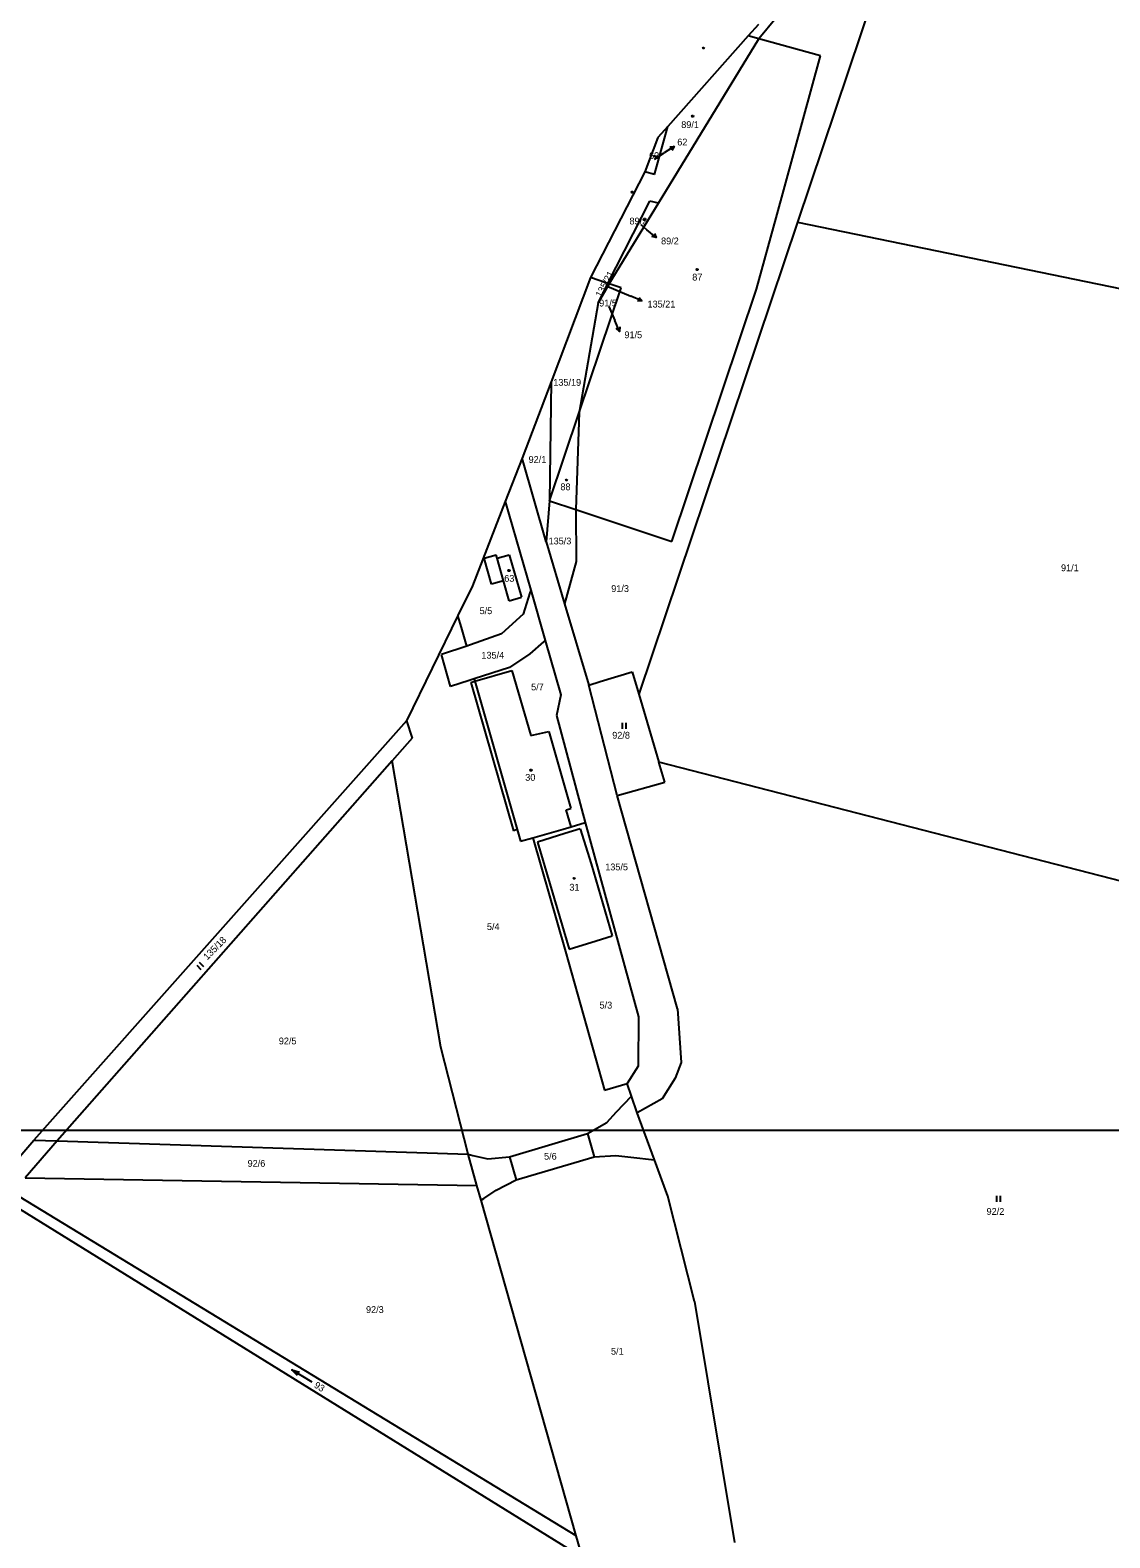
# Model space of a CAD drawing. Extents: x -752500 to -750336, y -1035826 to -1033500.
# Drawn here: x -751866.1 to -751596.3, y -1034101.8 to -1033725.2 of the extents above; entities that cross this region are included whole.
import ezdxf

# ---------------------------------------------------------------- set-up
doc = ezdxf.new("R2010")
doc.units = 0
for name, color, linetype in [('Default', 7, 'Continuous'), ('Hranice kat_území', 7, 'Continuous'), ('Hranice parcel', 7, 'Continuous'), ('ML1000', 7, 'Continuous'), ('Parcelní čísla', 7, 'Continuous'), ('Pop  PČ popisy', 7, 'Continuous'), ('Vnitřní kresba', 7, 'Continuous'), ('Značky budov', 7, 'Continuous'), ('Značky kultur', 7, 'Continuous')]:
    doc.layers.add(name, color=color, linetype=linetype)

# ---------------------------------------------------------------- blocks, each defined once
blk = doc.blocks.new('306')
at = {"layer": 'Default'}
for p, q in [((-0.5, 1.5), (-0.5, 0)), ((0.5, 0), (0.5, 1.5))]:
    blk.add_line(p, q, dxfattribs=at)
blk = doc.blocks.new('802')
at = {"layer": 'Default'}
blk.add_line((-3, 0), (3, 0), dxfattribs=at)
blk.add_lwpolyline([(1, 0.5), (3, 0), (1, -0.5)], dxfattribs=at)
blk = doc.blocks.new('10292')
at = {"layer": 'Default'}
blk.add_line((0, 3), (0, 0), dxfattribs=at)
blk.add_lwpolyline([(-0.5, 2), (0, 3), (0.5, 2)], dxfattribs=at)
blk = doc.blocks.new('402')
at = {"layer": 'Default'}
blk.add_lwpolyline([(0.09, 0.15), (0.18, 0), (0.09, -0.15), (-0.09, -0.15), (-0.18, 0), (-0.09, 0.15), (0.09, 0.15)], dxfattribs=at)

msp = doc.modelspace()

# ---------------------------------------------------------------- linework, layer by layer
at = {"layer": 'Hranice kat_území'}
for p, q in [((-751686.7, -1033726.57), (-751706.79, -1033749.21)), ((-751684.07, -1033723.74), (-751686.7, -1033726.57)), ((-751706.79, -1033749.21), (-751709.24, -1033751.97)), ((-751709.24, -1033751.97), (-751712.49, -1033760.52)), ((-751712.49, -1033760.52), (-751726.1, -1033786.95)), ((-751726.1, -1033786.95), (-751735.93, -1033813.02)), ((-751735.93, -1033813.02), (-751743.12, -1033832.07)), ((-751743.12, -1033832.07), (-751747.38, -1033842.95)), ((-751747.38, -1033842.95), (-751755.6, -1033863.97)), ((-751755.6, -1033863.97), (-751759.23, -1033871.39)), ((-751759.23, -1033871.39), (-751772.1, -1033897.72)), ((-751772.1, -1033897.72), (-751865.22, -1034002.43)), ((-751900.01, -1034043.01), (-751865.22, -1034002.43))]:
    msp.add_line(p, q, dxfattribs=at)
at = {"layer": 'Hranice parcel'}
for p, q in [((-751649.5, -1033699.28), (-751674.33, -1033773.12)), ((-751671.51, -1033712.21), (-751684.01, -1033727.32)), ((-751684.01, -1033727.32), (-751686.7, -1033726.57)), ((-751709.08, -1033768.39), (-751684.01, -1033727.32)), ((-751668.6, -1033731.57), (-751684.01, -1033727.32)), ((-751679.67, -1033772.02), (-751668.6, -1033731.57)), ((-751710.08, -1033761.2), (-751706.79, -1033749.21)), ((-751710.08, -1033761.2), (-751712.49, -1033760.52)), ((-751721.77, -1033788.42), (-751711.24, -1033767.89)), ((-751721.39, -1033788.55), (-751709.08, -1033768.39)), ((-751709.08, -1033768.39), (-751711.24, -1033767.89)), ((-751684.56, -1033789.88), (-751679.67, -1033772.02)), ((-751674.33, -1033773.12), (-751714, -1033891.06)), ((-751674.33, -1033773.12), (-751500.87, -1033808.86)), ((-751721.77, -1033788.42), (-751726.1, -1033786.95)), ((-751728.9, -1033820.71), (-751718.44, -1033789.55)), ((-751724.13, -1033793.3), (-751721.77, -1033788.42)), ((-751721.39, -1033788.55), (-751724.13, -1033793.3)), ((-751721.39, -1033788.55), (-751721.77, -1033788.42)), ((-751718.44, -1033789.55), (-751721.39, -1033788.55)), ((-751705.73, -1033852.93), (-751684.56, -1033789.88)), ((-751724.13, -1033793.3), (-751728.9, -1033820.71)), ((-751735.93, -1033813.02), (-751736.29, -1033842.73)), ((-751736.29, -1033842.73), (-751728.9, -1033820.71)), ((-751728.9, -1033820.71), (-751729.71, -1033844.93)), ((-751737.18, -1033852.97), (-751743.12, -1033832.07)), ((-751747.38, -1033842.95), (-751740.99, -1033865.03)), ((-751736.29, -1033842.73), (-751737.18, -1033852.97)), ((-751736.29, -1033842.73), (-751729.71, -1033844.93)), ((-751729.71, -1033844.93), (-751705.73, -1033852.93)), ((-751729.71, -1033844.93), (-751729.68, -1033857.86)), ((-751737.18, -1033852.97), (-751732.54, -1033868.49)), ((-751752.63, -1033857.07), (-751749.65, -1033856.23)), ((-751750.79, -1033863.54), (-751752.63, -1033857.07)), ((-751749.4, -1033857.1), (-751749.65, -1033856.23)), ((-751749.4, -1033857.1), (-751746.42, -1033856.24)), ((-751746.42, -1033856.24), (-751743.33, -1033866.83)), ((-751729.68, -1033857.86), (-751732.54, -1033868.49)), ((-751747.81, -1033862.69), (-751750.79, -1033863.54)), ((-751746.39, -1033867.7), (-751747.81, -1033862.69)), ((-751741.21, -1033865.7), (-751742.93, -1033871.04)), ((-751740.99, -1033865.03), (-751741.21, -1033865.7)), ((-751740.99, -1033865.03), (-751737.37, -1033877.6)), ((-751746.39, -1033867.7), (-751743.33, -1033866.83)), ((-751732.54, -1033868.49), (-751726.47, -1033888.81)), ((-751742.93, -1033871.04), (-751748.35, -1033875.98)), ((-751748.35, -1033875.98), (-751756.09, -1033878.73)), ((-751737.37, -1033877.6), (-751737.82, -1033877.99)), ((-751737.37, -1033877.6), (-751733.48, -1033891.19)), ((-751756.97, -1033879.02), (-751763.29, -1033881.13)), ((-751761.06, -1033889.12), (-751763.29, -1033881.13)), ((-751756.09, -1033878.73), (-751756.97, -1033879.02)), ((-751741.23, -1033880.94), (-751746.31, -1033884.36)), ((-751737.82, -1033877.99), (-751741.23, -1033880.94)), ((-751746.31, -1033884.36), (-751755.12, -1033887.2)), ((-751754.96, -1033887.81), (-751745.73, -1033885.12)), ((-751745.73, -1033885.12), (-751740.96, -1033901.39)), ((-751756.41, -1033887.62), (-751761.06, -1033889.12)), ((-751755.12, -1033887.2), (-751756.41, -1033887.62)), ((-751755.96, -1033888.09), (-751754.96, -1033887.81)), ((-751755.96, -1033888.09), (-751745.29, -1033925.15)), ((-751755.12, -1033887.2), (-751754.96, -1033887.81)), ((-751726.47, -1033888.81), (-751723.64, -1033887.9)), ((-751719.38, -1033916.32), (-751726.47, -1033888.81)), ((-751723.64, -1033887.9), (-751715.65, -1033885.47)), ((-751715.65, -1033885.47), (-751714, -1033891.06)), ((-751733.48, -1033891.19), (-751734.54, -1033896.35)), ((-751714, -1033891.06), (-751709, -1033908.01)), ((-751734.54, -1033896.35), (-751727.45, -1033923.08)), ((-751772.1, -1033897.72), (-751770.62, -1033902.06)), ((-751770.62, -1033902.06), (-751775.63, -1033907.74)), ((-751740.96, -1033901.39), (-751736.49, -1033900.33)), ((-751736.49, -1033900.33), (-751731.03, -1033919.59)), ((-751775.63, -1033907.74), (-751859.34, -1034002.62)), ((-751763.47, -1033979.26), (-751775.63, -1033907.74)), ((-751532.72, -1033953.48), (-751709, -1033908.01)), ((-751707.53, -1033912.99), (-751709, -1033908.01)), ((-751719.38, -1033916.32), (-751707.53, -1033912.99)), ((-751704.33, -1033969.64), (-751719.38, -1033916.32)), ((-751732.17, -1033919.91), (-751731.03, -1033919.59)), ((-751730.93, -1033924.18), (-751732.17, -1033919.91)), ((-751744.37, -1033924.89), (-751745.29, -1033925.15)), ((-751744.37, -1033924.89), (-751743.54, -1033927.8)), ((-751740.48, -1033926.92), (-751732.9, -1033924.75)), ((-751732.52, -1033925.84), (-751739.33, -1033928)), ((-751732.9, -1033924.75), (-751730.93, -1033924.18)), ((-751728.66, -1033924.7), (-751732.52, -1033925.84)), ((-751730.93, -1033924.18), (-751727.45, -1033923.08)), ((-751727.45, -1033923.08), (-751714.12, -1033971.65)), ((-751743.54, -1033927.8), (-751740.48, -1033926.92)), ((-751740.48, -1033926.92), (-751732.35, -1033955.36)), ((-751739.33, -1033928), (-751731.42, -1033954.79)), ((-751731.42, -1033954.79), (-751724.63, -1033952.67)), ((-751724.63, -1033952.67), (-751720.63, -1033951.41)), ((-751732.35, -1033955.36), (-751722.54, -1033989.94)), ((-751714.12, -1033971.65), (-751714.19, -1033983.94)), ((-751704.33, -1033969.64), (-751703.42, -1033983.08)), ((-751756.67, -1034005.98), (-751763.47, -1033979.26)), ((-751703.42, -1033983.08), (-751704.9, -1033986.94)), ((-751714.19, -1033983.94), (-751716.92, -1033988.33)), ((-751722.54, -1033989.94), (-751716.92, -1033988.33)), ((-751715.84, -1033991.47), (-751716.92, -1033988.33)), ((-751704.9, -1033986.94), (-751708.2, -1033992.17)), ((-751719.54, -1033995.41), (-751715.84, -1033991.47)), ((-751714.42, -1033995.62), (-751715.84, -1033991.47)), ((-751708.2, -1033992.17), (-751714.42, -1033995.62)), ((-751726.86, -1034000.83), (-751722, -1033998.05)), ((-751722, -1033998.05), (-751719.54, -1033995.41)), ((-751710.08, -1034007.36), (-751714.42, -1033995.62)), ((-751746.34, -1034006.65), (-751726.86, -1034000.83)), ((-751859.34, -1034002.62), (-751867.34, -1034011.88)), ((-751865.22, -1034002.43), (-751859.34, -1034002.62)), ((-751859.34, -1034002.62), (-751756.67, -1034005.98)), ((-751756.67, -1034005.98), (-751755.53, -1034006.28)), ((-751754.45, -1034013.82), (-751756.67, -1034005.98)), ((-751755.53, -1034006.28), (-751751.75, -1034007.11)), ((-751751.75, -1034007.11), (-751746.34, -1034006.65)), ((-751744.65, -1034012.41), (-751725.17, -1034006.61)), ((-751725.17, -1034006.61), (-751719.71, -1034006.3)), ((-751719.71, -1034006.3), (-751716.02, -1034006.71)), ((-751716.02, -1034006.71), (-751710.08, -1034007.36)), ((-751706.71, -1034016.5), (-751710.08, -1034007.36)), ((-751867.34, -1034011.88), (-751754.45, -1034013.82)), ((-751749.65, -1034014.95), (-751744.65, -1034012.41)), ((-751729.63, -1034101.32), (-751870.54, -1034015.58)), ((-751753.41, -1034017.47), (-751754.45, -1034013.82)), ((-751752.74, -1034017.03), (-751749.65, -1034014.95)), ((-751700.05, -1034042.8), (-751706.71, -1034016.5)), ((-751728.11, -1034106.69), (-751872.23, -1034017.53)), ((-751753.41, -1034017.47), (-751752.74, -1034017.03)), ((-751729.63, -1034101.32), (-751753.41, -1034017.47)), ((-751700.05, -1034042.8), (-751690.1, -1034103.01)), ((-751728.11, -1034106.69), (-751729.63, -1034101.32))]:
    msp.add_line(p, q, dxfattribs=at)
for points in [[(-751756.97, -1033879.02), (-751758.34, -1033874.4), (-751759.23, -1033871.39)], [(-751728.66, -1033924.7), (-751725.93, -1033933.46), (-751720.63, -1033951.41)]]:
    msp.add_lwpolyline(points, dxfattribs=at)
at = {"layer": 'ML1000'}
msp.add_lwpolyline([(-752500, -1034000), (-751875, -1034000), (-751250, -1034000)], dxfattribs=at)
at = {"layer": 'Pop  PČ popisy'}
for p, q in [((-751710.11, -1033757.35), (-751707.7, -1033755.83)), ((-751713.49, -1033773.7), (-751711.96, -1033775.02)), ((-751721.93, -1033789.08), (-751715.98, -1033791.59)), ((-751721.47, -1033794.19), (-751720.01, -1033797.66))]:
    msp.add_line(p, q, dxfattribs=at)
at = {"layer": 'Vnitřní kresba'}
for p, q in [((-751747.81, -1033862.69), (-751749.4, -1033857.1)), ((-751754.96, -1033887.81), (-751744.37, -1033924.89)), ((-751726.86, -1034000.83), (-751725.17, -1034006.61)), ((-751746.34, -1034006.65), (-751744.65, -1034012.41))]:
    msp.add_line(p, q, dxfattribs=at)

# ---------------------------------------------------------------- block references
at = {"layer": 'Pop  PČ popisy'}
for p, rotation in [((-751707.7, -1033755.83), -57.650172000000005), ((-751711.96, -1033775.02), -130.644995), ((-751715.98, -1033791.59), -112.82600699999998), ((-751720.01, -1033797.66), -157.115645)]:
    msp.add_blockref('10292', p, dxfattribs=dict(at, rotation=rotation))
at = {"layer": 'Značky budov'}
for p in [(-751697.84, -1033729.63), (-751700.54, -1033746.62), (-751710.01, -1033756.6), (-751715.62, -1033765.65), (-751712.68, -1033772.47), (-751699.39, -1033784.95), (-751732.07, -1033837.54), (-751746.45, -1033860.17), (-751740.95, -1033910.05), (-751730.17, -1033937.06)]:
    msp.add_blockref('402', p, dxfattribs=at)
at = {"layer": 'Značky kultur'}
for p in [(-751717.7, -1033899.74), (-751624.08, -1034017.84)]:
    msp.add_blockref('306', p, dxfattribs=at)
for name, p, rotation in [('306', (-751823.13, -1033959.49), 42.284285), ('802', (-751798.21, -1034061.39), 148.338773)]:
    msp.add_blockref(name, p, dxfattribs=dict(at, rotation=rotation))

# ---------------------------------------------------------------- texts
at = {"layer": 'Parcelní čísla'}
for s, p in [('89/1', (-751703.4, -1033749.61)), ('62', (-751704.39, -1033753.96)), ('62', (-751711.45, -1033757.35)), ('89/2', (-751716.33, -1033773.7)), ('89/2', (-751708.44, -1033778.67)), ('87', (-751700.65, -1033787.71)), ('91/5', (-751723.91, -1033794.19)), ('135/21', (-751711.83, -1033794.45)), ('91/5', (-751717.6, -1033802.12)), ('135/19', (-751735.38, -1033814)), ('92/1', (-751741.55, -1033833.27)), ('88', (-751733.6, -1033840.09)), ('135/3', (-751736.56, -1033853.63)), ('91/1', (-751608.48, -1033860.33)), ('63', (-751747.64, -1033862.96)), ('91/3', (-751720.9, -1033865.52)), ('5/5', (-751753.8, -1033871.05)), ('135/4', (-751753.35, -1033882.17)), ('5/7', (-751740.92, -1033890.09)), ('92/8', (-751720.65, -1033902.16)), ('30', (-751742.39, -1033912.68)), ('135/5', (-751722.4, -1033935.06)), ('31', (-751731.36, -1033940.13)), ('5/4', (-751751.97, -1033949.97)), ('5/3', (-751723.82, -1033969.59)), ('92/5', (-751803.98, -1033978.53)), ('5/6', (-751737.69, -1034007.35)), ('92/6', (-751811.78, -1034009.12)), ('92/2', (-751627.08, -1034021.13)), ('92/3', (-751782.19, -1034045.64)), ('5/1', (-751720.96, -1034056.06))]:
    msp.add_text(s, height=1.7, dxfattribs=at).set_placement(p)
for s, rotation, p in [('135/21', 61.879, (-751723.44, -1033792.04)), ('135/18', 45.034, (-751821.85, -1033957.55)), ('93', 328.133, (-751795.33, -1034064.12))]:
    msp.add_text(s, height=1.7, rotation=rotation, dxfattribs=at).set_placement(p)

doc.saveas('drawing.dxf')
